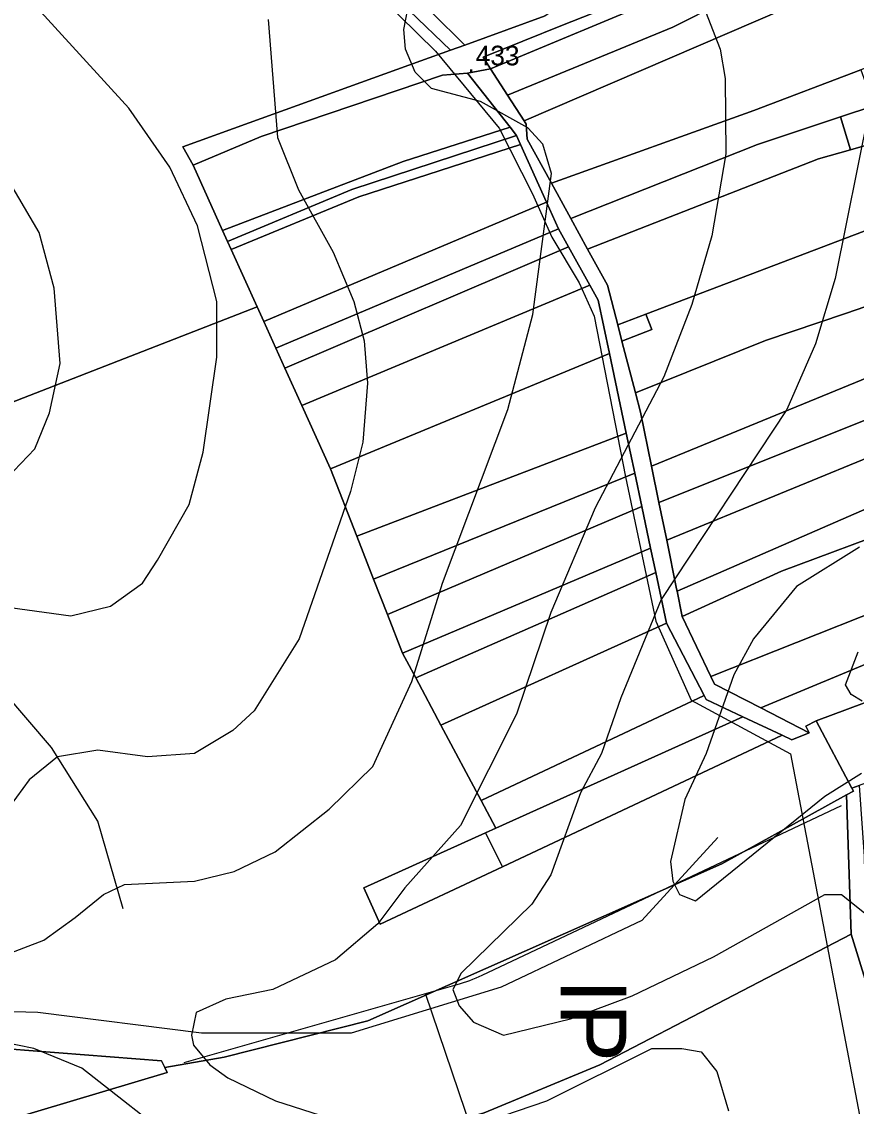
# Model space of a CAD drawing. Extents: x -510989 to -501240, y -1184665 to -1176089.
# Drawn here: x -509914.8 to -509660.1, y -1179416.7 to -1179085.6 of the extents above; entities that cross this region are included whole.
import ezdxf

# ---------------------------------------------------------------- set-up
doc = ezdxf.new("R2010")
doc.units = 0
for name, color, linetype in [('NAVRH_interakcni_prvky', 7, 'Continuous'), ('orna_puda', 7, 'Continuous'), ('ostatni_plocha_x_jina_plocha', 7, 'Continuous'), ('ostatni_plocha_x_neplodna_puda', 7, 'Continuous'), ('ostatni_plocha_x_ostatni_komunikace', 7, 'Continuous'), ('ovocny_sad', 7, 'Continuous'), ('STAV_systematicke_odvodneni', 7, 'Continuous'), ('STAV_vyrazne_udolnice', 7, 'Continuous'), ('trvaly_travni_porost', 7, 'Continuous'), ('vrstevnice_01', 7, 'Continuous'), ('vrstevnice_02', 7, 'Continuous'), ('vrstevnice_05', 7, 'Continuous'), ('zahrada', 7, 'Continuous'), ('zastavena_plocha_a_nadvori', 7, 'Continuous')]:
    doc.layers.add(name, color=color, linetype=linetype)

msp = doc.modelspace()

# ---------------------------------------------------------------- linework, layer by layer
at = {"layer": 'NAVRH_interakcni_prvky'}
for p, q in [((-509774.27, -1179376.64), (-509664.64, -1179324.83)), ((-509865.15, -1179403.29), (-509781.9, -1179379.51)), ((-509791.67, -1179382.12), (-509733.43, -1179553.31))]:
    msp.add_line(p, q, dxfattribs=at)
msp.add_arc((-509795.64, -1179331.43), 50, 285.9458, 295.292, dxfattribs=at)
at = {"layer": 'orna_puda'}
for points in [[(-509778.76, -1179101.34), (-509765.75, -1179117.86), (-509798.38, -1179128.32), (-509853.5, -1179149.34), (-509862.49, -1179129.46), (-509841.72, -1179120.7), (-509786.41, -1179101.98)], [(-509763.78, -1179120.36), (-509814, -1179136.9), (-509851.96, -1179152.73), (-509853.5, -1179149.34), (-509798.38, -1179128.32), (-509765.75, -1179117.86)], [(-509762.55, -1179123.09), (-509811.95, -1179139.08), (-509850.86, -1179155.16), (-509851.96, -1179152.73), (-509814, -1179136.9), (-509763.78, -1179120.36)], [(-509811.95, -1179139.08), (-509762.55, -1179123.09), (-509754.64, -1179140.76), (-509840.94, -1179177.11), (-509842.94, -1179172.68), (-509850.86, -1179155.16)], [(-509751.02, -1179148.83), (-509837.24, -1179185.28), (-509840.94, -1179177.11), (-509754.64, -1179140.76)], [(-509747.92, -1179154.38), (-509834.49, -1179191.36), (-509837.24, -1179185.28), (-509751.02, -1179148.83)], [(-509741.43, -1179166.01), (-509829.34, -1179202.75), (-509834.49, -1179191.36), (-509747.92, -1179154.38)], [(-509738.84, -1179170.63), (-509735.41, -1179186.92), (-509820.57, -1179222.13), (-509829.34, -1179202.75), (-509741.43, -1179166.01)], [(-509727.71, -1179223.42), (-509807.41, -1179255.75), (-509812.54, -1179242.66), (-509730.29, -1179211.19)], [(-509725.57, -1179233.58), (-509803.17, -1179266.58), (-509807.41, -1179255.75), (-509727.71, -1179223.42)], [(-509722.88, -1179246.33), (-509798.54, -1179278.41), (-509803.17, -1179266.58), (-509725.57, -1179233.58)], [(-509721.32, -1179253.72), (-509794.56, -1179285.89), (-509798.54, -1179278.41), (-509722.88, -1179246.33)], [(-509718.05, -1179269.19), (-509786.85, -1179300.38), (-509794.56, -1179285.89), (-509721.32, -1179253.72)], [(-509706.55, -1179291.3), (-509774.6, -1179323.37), (-509786.85, -1179300.38), (-509718.05, -1179269.19)], [(-509705.94, -1179292.47), (-509694.73, -1179297.77), (-509770.12, -1179331.8), (-509774.6, -1179323.37), (-509706.55, -1179291.3)], [(-509694.73, -1179297.77), (-509682.76, -1179303.42), (-509768.08, -1179343.54), (-509773.3, -1179333.24), (-509770.12, -1179331.8)], [(-509773.3, -1179333.24), (-509768.08, -1179343.54), (-509805.37, -1179361.09), (-509810.38, -1179350.02)]]:
    msp.add_lwpolyline(points, close=True, dxfattribs=at)
msp.add_lwpolyline([(-509917.23, -1179465.75), (-509863.35, -1179455.49), (-509821.13, -1179438.42), (-509807.97, -1179428.77), (-509773.7, -1179418.63), (-509738.37, -1179404.04), (-509661.7, -1179364.17), (-509646.38, -1179413.87), (-509629.15, -1179456.33), (-509594.88, -1179508.89), (-509601.99, -1179511.21), (-509593.87, -1179546.25), (-509579.56, -1179608.03), (-509575.69, -1179640.23), (-509571.98, -1179686.17), (-509598.04, -1179695.37), (-509681.32, -1179724.23), (-509784.58, -1179762.55), (-509812.55, -1179772.46), (-509843.4, -1179782.08), (-509873.28, -1179791.41), (-509898.66, -1179798.48), (-509924.84, -1179805.39)], dxfattribs=at)
at = {"layer": 'ostatni_plocha_x_jina_plocha'}
msp.add_lwpolyline([(-509732.9, -1179178.2), (-509724.33, -1179174.94), (-509722.52, -1179179.62), (-509731.61, -1179183.14)], close=True, dxfattribs=at)
at = {"layer": 'ostatni_plocha_x_neplodna_puda'}
msp.add_lwpolyline([(-509927.02, -1179398.47), (-509872.09, -1179402.82), (-509871.1, -1179404.85), (-509870.34, -1179406.4), (-509919.68, -1179421.07), (-509940.2, -1179428.11), (-509941.22, -1179425.67), (-509946.24, -1179413.7), (-509948.61, -1179408.03), (-509983.6, -1179412.12), (-510061.56, -1179421.23), (-510103.58, -1179425.83), (-510103.66, -1179418.16), (-510007.29, -1179402.69)], close=True, dxfattribs=at)
at = {"layer": 'ostatni_plocha_x_ostatni_komunikace'}
for points in [[(-509655.18, -1179041.47), (-509628.27, -1179032.77), (-509665.13, -1179049.17), (-509674.98, -1179053.55), (-509698.18, -1179067.48), (-509717.48, -1179077.37), (-509771.74, -1179100.02), (-509774.01, -1179096.51), (-509749.75, -1179086.75), (-509725.48, -1179077), (-509724.94, -1179078.36), (-509714.76, -1179074.27), (-509673.87, -1179051.75), (-509665.97, -1179047.41)], [(-509771.74, -1179100.02), (-509766.54, -1179108.08), (-509761.48, -1179115.91), (-509760.83, -1179116.91), (-509760.53, -1179121.51), (-509753.17, -1179134.9), (-509747.22, -1179145.74), (-509742.1, -1179155.06), (-509736.08, -1179166.02), (-509732.9, -1179178.2), (-509731.61, -1179183.14), (-509727.5, -1179198.93), (-509725.97, -1179204.81), (-509722.6, -1179221.29), (-509720.34, -1179232.36), (-509717.98, -1179243.86), (-509714.95, -1179258.7), (-509714.81, -1179259.4), (-509713.22, -1179267.17), (-509704.48, -1179285.5), (-509703.35, -1179287.88), (-509689.29, -1179295.1), (-509674.52, -1179302.68), (-509679.75, -1179304.85), (-509682.76, -1179303.42), (-509694.73, -1179297.77), (-509705.94, -1179292.47), (-509706.55, -1179291.3), (-509718.05, -1179269.19), (-509721.32, -1179253.72), (-509722.88, -1179246.33), (-509725.57, -1179233.58), (-509727.71, -1179223.42), (-509730.29, -1179211.19), (-509735.41, -1179186.92), (-509738.84, -1179170.63), (-509741.43, -1179166.01), (-509747.92, -1179154.38), (-509751.02, -1179148.83), (-509754.64, -1179140.76), (-509762.55, -1179123.09), (-509763.78, -1179120.36), (-509765.75, -1179117.86), (-509778.76, -1179101.34)]]:
    msp.add_lwpolyline(points, close=True, dxfattribs=at)
for points in [[(-509789.64, -1179082.84), (-509779.58, -1179092.77), (-509783.93, -1179094.34), (-509808.93, -1179070.27)], [(-509725.48, -1179077), (-509749.75, -1179086.75), (-509774.01, -1179096.51), (-509771.74, -1179100.02), (-509778.76, -1179101.34), (-509786.41, -1179101.98), (-509841.72, -1179120.7), (-509862.49, -1179129.46), (-509865.57, -1179123.81), (-509845.35, -1179116.51), (-509793.03, -1179097.62), (-509783.93, -1179094.34), (-509779.58, -1179092.77), (-509766.75, -1179088.14), (-509755.1, -1179083.84)], [(-509629.15, -1179456.33), (-509646.38, -1179413.87), (-509661.7, -1179364.17), (-509663.1, -1179321.65), (-509660.99, -1179320.48), (-509661.48, -1179319.55), (-509659.25, -1179318.74), (-509657.71, -1179340.46), (-509657.22, -1179363.64), (-509657.19, -1179365.06), (-509652.58, -1179379.38), (-509647.95, -1179393.76), (-509642.47, -1179410.82), (-509635.67, -1179431.97)]]:
    msp.add_lwpolyline(points, dxfattribs=at)
at = {"layer": 'ovocny_sad'}
msp.add_lwpolyline([(-509655.12, -1179070.02), (-509651.96, -1179068.66), (-509649.93, -1179074.31), (-509648.54, -1179078.17), (-509643.67, -1179076.41), (-509645.05, -1179072.56), (-509627.89, -1179066.39), (-509619.17, -1179085.35), (-509620.91, -1179085.91), (-509643.4, -1179094.46), (-509651.09, -1179097.39), (-509658.77, -1179100.31), (-509691.37, -1179112.71), (-509753.17, -1179134.9), (-509760.53, -1179121.51), (-509760.83, -1179116.91), (-509761.48, -1179115.91)], close=True, dxfattribs=at)
at = {"layer": 'STAV_systematicke_odvodneni'}
for p, q in [((-509805.74, -1179077.69), (-509788.48, -1179094.66)), ((-509788.48, -1179094.66), (-509769.05, -1179118.11)), ((-509769.05, -1179118.11), (-509758.87, -1179138.16)), ((-509758.87, -1179138.16), (-509753.01, -1179151.42)), ((-509753.01, -1179151.42), (-509744.69, -1179165.31)), ((-509744.69, -1179165.31), (-509740.06, -1179175.49)), ((-509740.06, -1179175.49), (-509730.5, -1179224.54)), ((-509730.5, -1179224.54), (-509721.25, -1179268.65)), ((-509721.25, -1179268.65), (-509710.46, -1179292.72)), ((-509710.46, -1179292.72), (-509680.24, -1179309.07)), ((-509680.24, -1179309.07), (-509654.64, -1179442.96))]:
    msp.add_line(p, q, dxfattribs=at)
at = {"layer": 'STAV_vyrazne_udolnice'}
for points in [[(-509883.84, -1179356.4), (-509891.58, -1179329.69), (-509905.64, -1179307.19), (-509927.45, -1179281.88), (-509944.33, -1179270.63), (-509967.54, -1179261.49), (-509981.61, -1179254.46), (-510002.71, -1179234.77), (-510023.1, -1179218.6), (-510049.13, -1179205.95)], [(-509702.38, -1179334.61), (-509725.59, -1179359.92), (-509768.49, -1179380.3), (-509814.21, -1179394.37), (-509859.93, -1179394.37), (-509909.86, -1179388.04), (-509935.89, -1179387.34), (-509971.06, -1179388.74), (-510005.52, -1179389.44), (-510049.83, -1179376.09), (-510106.1, -1179359.92), (-510129.31, -1179347.96), (-510163.07, -1179334.61)]]:
    msp.add_lwpolyline(points, dxfattribs=at)
at = {"layer": 'trvaly_travni_porost'}
for points in [[(-509808.93, -1179070.27), (-509783.93, -1179094.34), (-509793.03, -1179097.62), (-509845.35, -1179116.51), (-509865.57, -1179123.81), (-509862.49, -1179129.46), (-509853.5, -1179149.34), (-509851.96, -1179152.73), (-509850.86, -1179155.16), (-509842.94, -1179172.68), (-509929.99, -1179206.54)], [(-509929.99, -1179206.54), (-509842.94, -1179172.68), (-509840.94, -1179177.11), (-509837.24, -1179185.28), (-509834.49, -1179191.36), (-509829.34, -1179202.75), (-509820.57, -1179222.13), (-509812.54, -1179242.66), (-509807.41, -1179255.75), (-509803.17, -1179266.58), (-509798.54, -1179278.41), (-509794.56, -1179285.89), (-509786.85, -1179300.38), (-509774.6, -1179323.37), (-509770.12, -1179331.8), (-509773.3, -1179333.24), (-509810.38, -1179350.02), (-509805.37, -1179361.09), (-509768.08, -1179343.54), (-509682.76, -1179303.42), (-509679.75, -1179304.85), (-509674.52, -1179302.68), (-509675.55, -1179300.61), (-509672.41, -1179299.05), (-509661.48, -1179319.55), (-509660.99, -1179320.48), (-509663.1, -1179321.65), (-509701.11, -1179342.69), (-509809.11, -1179390.6), (-509852.98, -1179401.65), (-509871.1, -1179404.85), (-509872.09, -1179402.82), (-509927.02, -1179398.47)], [(-509919.68, -1179421.07), (-509870.34, -1179406.4), (-509871.1, -1179404.85), (-509852.98, -1179401.65), (-509809.11, -1179390.6), (-509701.11, -1179342.69), (-509663.1, -1179321.65), (-509661.7, -1179364.17), (-509738.37, -1179404.04), (-509773.7, -1179418.63), (-509807.97, -1179428.77), (-509821.13, -1179438.42), (-509863.35, -1179455.49), (-509917.23, -1179465.75)]]:
    msp.add_lwpolyline(points, dxfattribs=at)
at = {"layer": 'vrstevnice_01'}
for points in [[(-509714.91, -1179060), (-509701.69, -1179094), (-509700.09, -1179103), (-509699.91, -1179126), (-509704.19, -1179151), (-509710.31, -1179172), (-509718.81, -1179194), (-509739.81, -1179234), (-509753.31, -1179266), (-509763.81, -1179297), (-509780.91, -1179331), (-509797.91, -1179350), (-509806.09, -1179361), (-509819, -1179372), (-509838.19, -1179381), (-509852.5, -1179384), (-509861.5, -1179388), (-509863, -1179395), (-509862.31, -1179398), (-509857.41, -1179404), (-509851.91, -1179408), (-509837.31, -1179415), (-509815.5, -1179422)], [(-509839.59, -1179085), (-509836.69, -1179121), (-509830.31, -1179137), (-509819.69, -1179156), (-509813.41, -1179171), (-509810.31, -1179183), (-509809.31, -1179196), (-509810.69, -1179214), (-509814.5, -1179229), (-509830.09, -1179274), (-509843.81, -1179296), (-509850.31, -1179302), (-509862.09, -1179309), (-509876.41, -1179310), (-509891.5, -1179308), (-509903.81, -1179310), (-509912.5, -1179317), (-509918.31, -1179325)], [(-509919.31, -1179225), (-509910.81, -1179216), (-509906.31, -1179205), (-509903, -1179190), (-509904.91, -1179167), (-509909.41, -1179150), (-509922.97, -1179127.1)], [(-509659.19, -1179246), (-509678.41, -1179258), (-509691.5, -1179274), (-509697.5, -1179285), (-509705.91, -1179309), (-509712.41, -1179323), (-509716.81, -1179342), (-509716.09, -1179348), (-509714.09, -1179352), (-509709.19, -1179354), (-509669.69, -1179322), (-509658.5, -1179315)], [(-509772.19, -1179421), (-509754.5, -1179415), (-509722.5, -1179399), (-509713.31, -1179399), (-509707.41, -1179400), (-509702.69, -1179406), (-509699.09, -1179418)]]:
    msp.add_lwpolyline(points, dxfattribs=at)
at = {"layer": 'vrstevnice_02'}
for points in [[(-509929.09, -1179374), (-509908, -1179366), (-509898.5, -1179359), (-509889.81, -1179352), (-509883.41, -1179349), (-509862, -1179348), (-509849.91, -1179345), (-509837.41, -1179339), (-509820.91, -1179326), (-509807.59, -1179313), (-509795.69, -1179287), (-509786.41, -1179257), (-509766.41, -1179204), (-509758.81, -1179175), (-509753.09, -1179132), (-509755.81, -1179123), (-509760.31, -1179118), (-509774.81, -1179110), (-509789.69, -1179106), (-509794.69, -1179101), (-509797.69, -1179094), (-509798.19, -1179088), (-509796.41, -1179079)], [(-509921.19, -1179264), (-509899.81, -1179267), (-509887.69, -1179264), (-509877.91, -1179257), (-509873.31, -1179250), (-509863.69, -1179233), (-509859.41, -1179217), (-509855.19, -1179188), (-509855.19, -1179171), (-509861.09, -1179148), (-509869.59, -1179130), (-509882.09, -1179112), (-509912.19, -1179079)], [(-509656.31, -1179113), (-509666.59, -1179164), (-509672.59, -1179184), (-509681.31, -1179204), (-509719.69, -1179262), (-509732, -1179292), (-509737.91, -1179309), (-509744.31, -1179321), (-509753.31, -1179346), (-509759.09, -1179355), (-509780.69, -1179376), (-509783.19, -1179381), (-509781.31, -1179386), (-509776.91, -1179391), (-509767.81, -1179395), (-509747.31, -1179390), (-509728.5, -1179383), (-509703.69, -1179371), (-509669.69, -1179352), (-509664.59, -1179352), (-509657.09, -1179358)], [(-509658.31, -1179293), (-509661.69, -1179291), (-509663.41, -1179288), (-509659.59, -1179278)], [(-509865.81, -1179429), (-509896.41, -1179405), (-509911.09, -1179399), (-509926.09, -1179396)]]:
    msp.add_lwpolyline(points, dxfattribs=at)
at = {"layer": 'zahrada'}
for points in [[(-509675.09, -1179028.39), (-509668.56, -1179042.01), (-509685.65, -1179048.43), (-509717.44, -1179067.1), (-509727.91, -1179070.59), (-509746.19, -1179078.11), (-509755.1, -1179083.84), (-509766.75, -1179088.14), (-509779.58, -1179092.77), (-509789.64, -1179082.84), (-509764.99, -1179072.37), (-509718.41, -1179052.58), (-509713.98, -1179050.11)], [(-509617.54, -1179042.46), (-509617.15, -1179042.79), (-509635.06, -1179048.64), (-509659.91, -1179060.04), (-509685.99, -1179072.02), (-509716.09, -1179087.3), (-509766.54, -1179108.08), (-509771.74, -1179100.02), (-509717.48, -1179077.37), (-509698.18, -1179067.48), (-509674.98, -1179053.55), (-509665.13, -1179049.17), (-509628.27, -1179032.77)], [(-509635.06, -1179048.64), (-509617.15, -1179042.79), (-509608.62, -1179049.96), (-509651.96, -1179068.66), (-509655.12, -1179070.02), (-509761.48, -1179115.91), (-509766.54, -1179108.08), (-509716.09, -1179087.3), (-509685.99, -1179072.02), (-509659.91, -1179060.04)], [(-509658.77, -1179100.31), (-509654.76, -1179111.29), (-509664.98, -1179114.7), (-509690.29, -1179123.14), (-509747.22, -1179145.74), (-509753.17, -1179134.9), (-509691.37, -1179112.71)], [(-509690.29, -1179123.14), (-509664.98, -1179114.7), (-509661.93, -1179124.72), (-509671.67, -1179127.47), (-509742.1, -1179155.06), (-509747.22, -1179145.74)], [(-509635.42, -1179117.23), (-509631.48, -1179131.03), (-509621.91, -1179128.29), (-509595.48, -1179122.59), (-509594.01, -1179133.16), (-509610.94, -1179135.63), (-509628.87, -1179140.16), (-509631.46, -1179140.81), (-509641.11, -1179143.25), (-509724.33, -1179174.94), (-509732.9, -1179178.2), (-509736.08, -1179166.02), (-509742.1, -1179155.06), (-509671.67, -1179127.47), (-509661.93, -1179124.72), (-509650.98, -1179121.63), (-509643.23, -1179119.44)], [(-509641.11, -1179143.25), (-509631.46, -1179140.81), (-509630.46, -1179144.48), (-509626.96, -1179157.3), (-509625.42, -1179162.91), (-509637.21, -1179165.75), (-509648.06, -1179169.43), (-509663.45, -1179174.66), (-509687.87, -1179182.95), (-509727.5, -1179198.93), (-509731.61, -1179183.14), (-509722.52, -1179179.62), (-509724.33, -1179174.94)], [(-509648.06, -1179169.43), (-509646.55, -1179175.38), (-509648.36, -1179175.84), (-509647.51, -1179179.18), (-509648.12, -1179179.34), (-509646.84, -1179184.36), (-509625.59, -1179177.55), (-509623.53, -1179183.77), (-509625.16, -1179184.25), (-509643.41, -1179189.57), (-509645.83, -1179190.42), (-509656.27, -1179194.11), (-509656.36, -1179194.14), (-509722.6, -1179221.29), (-509725.97, -1179204.81), (-509727.5, -1179198.93), (-509687.87, -1179182.95), (-509663.45, -1179174.66)], [(-509730.29, -1179211.19), (-509812.54, -1179242.66), (-509820.57, -1179222.13), (-509735.41, -1179186.92)], [(-509656.36, -1179194.14), (-509652.32, -1179205.23), (-509720.34, -1179232.36), (-509722.6, -1179221.29)], [(-509652.32, -1179205.23), (-509648.61, -1179215.43), (-509717.98, -1179243.86), (-509720.34, -1179232.36)], [(-509641.4, -1179212.78), (-509634.8, -1179210.36), (-509630.92, -1179224.77), (-509648.25, -1179230.48), (-509714.81, -1179259.4), (-509714.95, -1179258.7), (-509717.98, -1179243.86), (-509648.61, -1179215.43)], [(-509648.25, -1179233.99), (-509633.73, -1179228.9), (-509631.58, -1179235.05), (-509645.85, -1179239.51), (-509682.99, -1179253.37), (-509713.22, -1179267.17), (-509714.81, -1179259.4), (-509648.25, -1179230.48)], [(-509611.62, -1179232.48), (-509623.97, -1179235.7), (-509616.53, -1179251.98), (-509626.08, -1179254.35), (-509704.48, -1179285.5), (-509713.22, -1179267.17), (-509682.99, -1179253.37), (-509645.85, -1179239.51), (-509631.58, -1179235.05), (-509625.18, -1179233.05), (-509612.67, -1179229.14)], [(-509626.08, -1179254.35), (-509616.53, -1179251.98), (-509613.79, -1179263.63), (-509689.29, -1179295.1), (-509703.35, -1179287.88), (-509704.48, -1179285.5)], [(-509613.79, -1179263.63), (-509610.55, -1179277.44), (-509618.92, -1179280.18), (-509643.71, -1179288.3), (-509672.41, -1179299.05), (-509675.55, -1179300.61), (-509674.52, -1179302.68), (-509689.29, -1179295.1)], [(-509672.41, -1179299.05), (-509643.71, -1179288.3), (-509640.13, -1179299.56), (-509636.63, -1179310.53), (-509659.25, -1179318.74), (-509661.48, -1179319.55)]]:
    msp.add_lwpolyline(points, close=True, dxfattribs=at)
at = {"layer": 'zastavena_plocha_a_nadvori'}
msp.add_lwpolyline([(-509584.56, -1179091.11), (-509582.32, -1179098.71), (-509612.09, -1179109.09), (-509625.89, -1179113.91), (-509635.42, -1179117.23), (-509643.23, -1179119.44), (-509650.98, -1179121.63), (-509661.93, -1179124.72), (-509664.98, -1179114.7), (-509654.76, -1179111.29), (-509647.05, -1179108.72), (-509623.72, -1179100.94), (-509623.45, -1179100.85), (-509586.54, -1179086.15)], close=True, dxfattribs=at)

# ---------------------------------------------------------------- texts
at = {"layer": 'NAVRH_interakcni_prvky'}
msp.add_text('IP', height=20, rotation=270, dxfattribs=at).set_placement((-509750.3, -1179377.82))
at = {"layer": 'vrstevnice_05'}
for s, p in [('433', (-509776.25, -1179098.98)), ('.', (-509778.75, -1179101.09))]:
    msp.add_text(s, height=6, dxfattribs=at).set_placement(p)

doc.saveas('drawing.dxf')
